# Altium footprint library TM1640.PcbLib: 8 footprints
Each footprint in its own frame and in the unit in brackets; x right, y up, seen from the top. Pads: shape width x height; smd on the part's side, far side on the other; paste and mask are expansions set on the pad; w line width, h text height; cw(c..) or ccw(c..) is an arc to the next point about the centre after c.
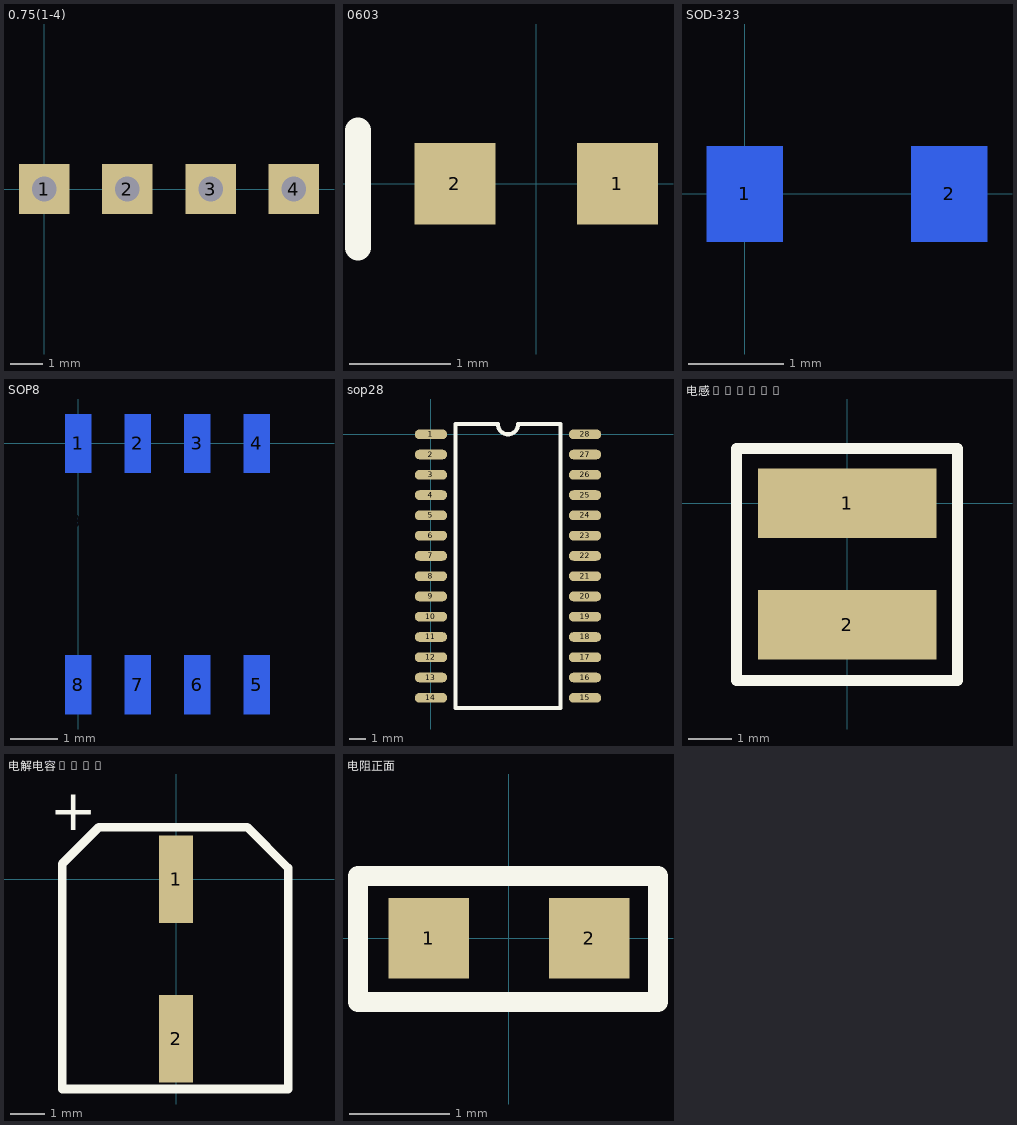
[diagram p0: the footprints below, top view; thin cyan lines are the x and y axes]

## 0.75(1-4) [mm]
pads (4):
  rect 1.54x1.54 hole 0.75: 1(0,0) 2(2.54,0) 3(5.08,0) 4(7.62,0)

## 0603 [mm]
pads (2):
  rect 0.8x0.8 smd: 1(0.8,0) 2(-0.8,0)
Top Overlay:
  lines w0.254: -1.754,-0.626 -1.754,0.524

## SOD-323 [mm]
pads (2):
  rect 0.8x1 smd far side: 1(0,0) 2(2.15,0)
Bottom Overlay:
  lines w0.2: 1.426,-0.54 1.426,0.588 ; 0.78,-0.566 1.397,0.051 0.78,0.669 0.78,-0.566

## SOP8 [mm]
pads (9):
  rect 0.55x1.25 smd far side: 1(0,0) 2(1.27,0) 3(2.54,0) 4(3.81,0) 5(3.81,-5.15) 6(2.54,-5.15) 7(1.27,-5.15) 8(0,-5.15)
  round 0.8 on Bottom Overlay: 9(-0.038,-1.664)
Bottom Overlay:
  lines w0.2: -0.787,-4.204 4.661,-4.204 4.661,-0.927 -0.787,-0.927 -0.787,-4.204

## sop28 [mil]
pads (28):
  oval 80x24 smd: 1(0,0) 2(0,-50) 3(0,-100) 4(0,-150) 5(0,-200) 6(0,-250) 7(0,-300) 8(0,-350) 9(0,-400) 10(0,-450) 11(0,-500) 12(0,-550) 13(0,-600) 14(0,-650) 15(380,-650) 16(380,-600) 17(380,-550) 18(380,-500) 19(380,-450) 20(380,-400) 21(380,-350) 22(380,-300) 23(380,-250) 24(380,-200) 25(380,-150) 26(380,-100) 27(380,-50) 28(380,0)
Top Overlay:
  lines w10: 60,-675 60,25 165,25 ccw(c190,25) 215,25 320,25 320,-675 60,-675

## 电感404018 [mm]
pads (2):
  rect 4.1x1.6 smd: 1(0,0) 2(0,-2.8)
Top Overlay:
  lines w0.25: -2.546,-4.077 2.534,-4.077 2.534,1.257 -2.546,1.257 -2.546,-4.077

## 电解电容47UF [mm]
pads (2):
  rect 1x2.55 smd: 1(0,0) 2(0,-4.65)
Top Overlay:
  lines w0.25: -3.322,-6.121 -3.322,0.457 -2.259,1.52 2.081,1.52 3.27,0.331 3.27,-6.121 -3.322,-6.121
  text "+" at -3.684,1.438 h1.2

## 电阻正面 [mm]
pads (2):
  rect 0.8x0.8 smd: 1(-0.8,0) 2(0.8,0)
Top Overlay:
  lines w0.2: -1.504,-0.638 -1.504,0.621 1.486,0.621 1.486,-0.638 -1.504,-0.638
